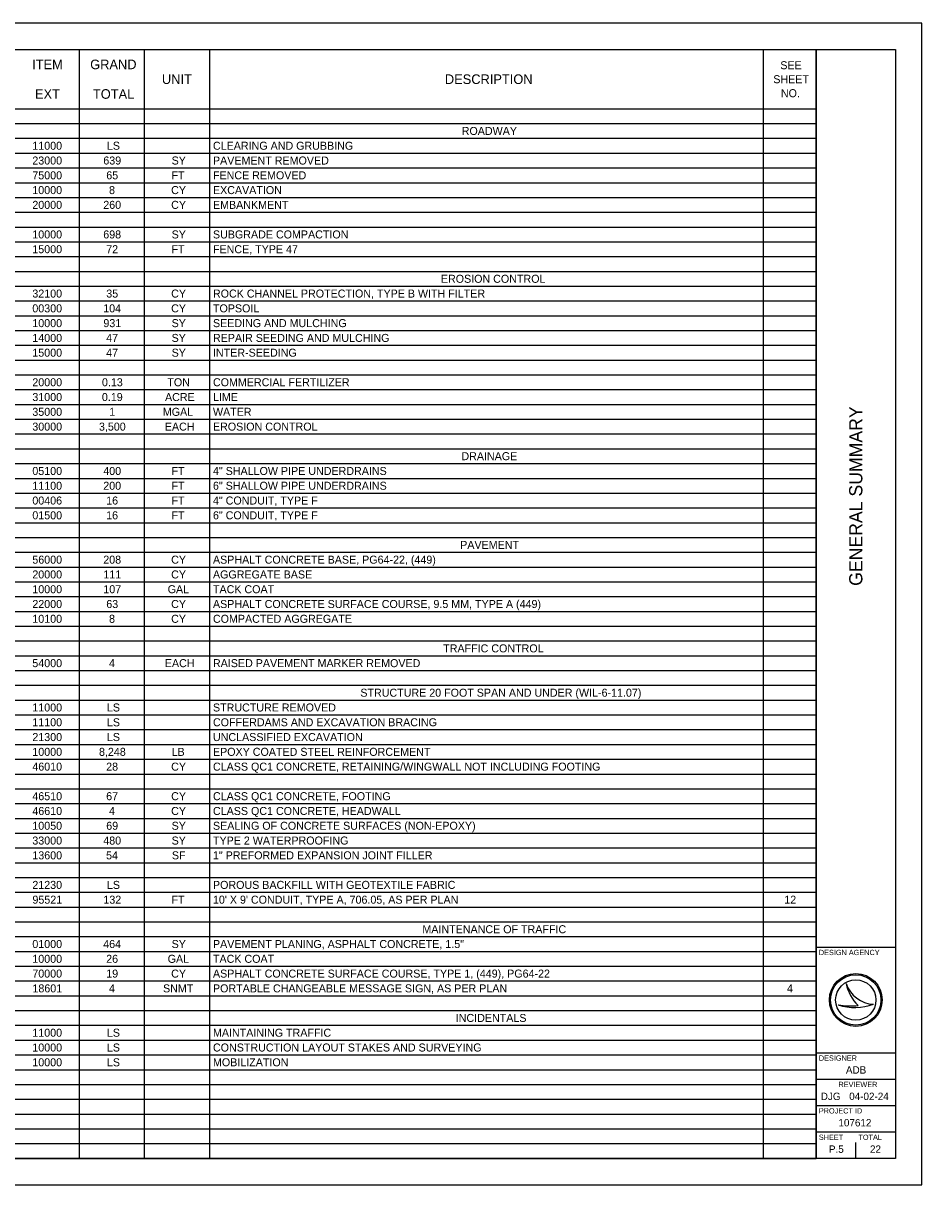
# Model space of a CAD drawing. Extents: x 0 to 34, y 0 to 22.
# Drawn here: x 16.98 to 34, y 0 to 22 of the extents above; entities that cross this region are included whole.
import ezdxf

# ---------------------------------------------------------------- set-up
doc = ezdxf.new("R2010")
doc.units = 0
for name, color, linetype in [('Default', 7, 'Continuous'), ('SH_Border', 7, 'Continuous'), ('SH_Cut_Line', 7, 'Continuous'), ('SH_Data', 7, 'Continuous')]:
    doc.layers.add(name, color=color, linetype=linetype)

msp = doc.modelspace()

# ---------------------------------------------------------------- linework, layer by layer
at = {"layer": 'Default'}
for p, q in [((1.5, 21.5), (32, 21.5)), ((18.035, 21.5), (18.035, 0.5)), ((19.27, 21.5), (19.27, 0.5)), ((20.505, 21.5), (20.505, 0.5)), ((30.995, 21.5), (30.995, 0.5)), ((32, 21.5), (32, 0.5)), ((1.5, 20.38), (32, 20.38)), ((1.5, 20.1), (32, 20.1)), ((1.5, 19.82), (32, 19.82)), ((1.5, 19.54), (32, 19.54)), ((1.5, 19.26), (32, 19.26)), ((1.5, 18.98), (32, 18.98)), ((1.5, 18.7), (32, 18.7)), ((1.5, 18.42), (32, 18.42)), ((1.5, 18.14), (32, 18.14)), ((1.5, 17.86), (32, 17.86)), ((1.5, 17.58), (32, 17.58)), ((1.5, 17.3), (32, 17.3)), ((1.5, 17.02), (32, 17.02)), ((1.5, 16.74), (32, 16.74)), ((1.5, 16.46), (32, 16.46)), ((1.5, 16.18), (32, 16.18)), ((1.5, 15.9), (32, 15.9)), ((1.5, 15.62), (32, 15.62)), ((1.5, 15.34), (32, 15.34)), ((1.5, 15.06), (32, 15.06)), ((1.5, 14.78), (32, 14.78)), ((1.5, 14.5), (32, 14.5)), ((1.5, 14.22), (32, 14.22)), ((1.5, 13.94), (32, 13.94)), ((1.5, 13.66), (32, 13.66)), ((1.5, 13.38), (32, 13.38)), ((1.5, 13.1), (32, 13.1)), ((1.5, 12.82), (32, 12.82)), ((1.5, 12.54), (32, 12.54)), ((1.5, 12.26), (32, 12.26)), ((1.5, 11.98), (32, 11.98)), ((1.5, 11.7), (32, 11.7)), ((1.5, 11.42), (32, 11.42)), ((1.5, 11.14), (32, 11.14)), ((1.5, 10.86), (32, 10.86)), ((1.5, 10.58), (32, 10.58)), ((1.5, 10.3), (32, 10.3)), ((1.5, 10.02), (32, 10.02)), ((1.5, 9.74), (32, 9.74)), ((1.5, 9.46), (32, 9.46)), ((1.5, 9.18), (32, 9.18)), ((1.5, 8.9), (32, 8.9)), ((1.5, 8.62), (32, 8.62)), ((1.5, 8.34), (32, 8.34)), ((1.5, 8.06), (32, 8.06)), ((1.5, 7.78), (32, 7.78)), ((1.5, 7.5), (32, 7.5)), ((1.5, 7.22), (32, 7.22)), ((1.5, 6.94), (32, 6.94)), ((1.5, 6.66), (32, 6.66)), ((1.5, 6.38), (32, 6.38)), ((1.5, 6.1), (32, 6.1)), ((1.5, 5.82), (32, 5.82)), ((1.5, 5.54), (32, 5.54)), ((1.5, 5.26), (32, 5.26)), ((1.5, 4.98), (32, 4.98)), ((1.5, 4.7), (32, 4.7)), ((1.5, 4.42), (32, 4.42)), ((1.5, 4.14), (32, 4.14)), ((1.5, 3.86), (32, 3.86)), ((1.5, 3.58), (32, 3.58)), ((1.5, 3.3), (32, 3.3)), ((1.5, 3.02), (32, 3.02)), ((1.5, 2.74), (32, 2.74)), ((1.5, 2.46), (32, 2.46)), ((1.5, 2.18), (32, 2.18)), ((1.5, 1.9), (32, 1.9)), ((1.5, 1.62), (32, 1.62)), ((1.5, 1.34), (32, 1.34)), ((1.5, 1.06), (32, 1.06)), ((1.5, 0.78), (32, 0.78)), ((1.5, 0.5), (32, 0.5))]:
    msp.add_line(p, q, dxfattribs=at)
at = {"layer": 'SH_Border'}
for p, q in [((32, 0.5), (32, 21.5)), ((32, 4.5), (33.5, 4.5)), ((32, 2.5), (33.5, 2.5)), ((32, 2), (33.5, 2)), ((32, 1.5), (33.5, 1.5)), ((32, 1), (33.5, 1))]:
    msp.add_line(p, q, dxfattribs=at)
msp.add_lwpolyline([(1.5, 21.5), (33.5, 21.5), (33.5, 0.5), (1.5, 0.5)], close=True, dxfattribs=at)
at = {"layer": 'SH_Cut_Line'}
msp.add_lwpolyline([(0, 0), (34, 0), (34, 22), (0, 22)], close=True, dxfattribs=at)
at = {"layer": 'SH_Data'}
for p, q in [((32.567, 3.81), (32.567, 3.81)), ((32.417, 3.41), (32.417, 3.41)), ((32.75, 3.5), (32.75, 3.5)), ((33.087, 3.419), (33.087, 3.419)), ((32.375, 0.675), (32.375, 0.675)), ((32.75, 0.5), (32.75, 0.8))]:
    msp.add_line(p, q, dxfattribs=at)
for radius in [0.5, 0.477, 0.477, 0.382]:
    msp.add_circle((32.75, 3.5), radius, dxfattribs=at)
for centre, radius, start, end in [((33.116, 3.998), 0.58, 198.9257, 198.9319), ((33.347, 3.97), 0.796, 191.6379, 191.6421), ((33.116, 3.998), 0.58, 198.9319, 267.1657), ((33.347, 3.97), 0.796, 191.6421, 226.0947), ((32.739, 4.37), 1.013, 251.4576, 290.0832), ((32.648, 4.654), 1.266, 259.4964, 259.4995), ((32.739, 4.37), 1.013, 251.4527, 251.4576), ((32.648, 4.654), 1.266, 259.4995, 276.6672)]:
    msp.add_arc(centre, radius, start, end, dxfattribs=at)

# ---------------------------------------------------------------- texts
at = {"layer": 'Default'}
for s, height, p in [('ITEM', 0.1818, (17.145, 21.129)), ('GRAND', 0.1818, (18.245, 21.129)), ('SEE ', 0.1515, (31.32, 21.129)), ('UNIT', 0.1818, (19.604, 20.849)), ('DESCRIPTION', 0.18184, (24.965, 20.849)), ('SHEET ', 0.1515, (31.187, 20.864)), ('EXT', 0.1818, (17.199, 20.569)), ('TOTAL', 0.1818, (18.297, 20.569)), ('NO.', 0.1515, (31.331, 20.599)), ('ROADWAY', 0.1515, (25.284, 19.884)), ('11000', 0.1515, (17.149, 19.604)), ('LS', 0.1515, (18.562, 19.604)), ('CLEARING AND GRUBBING', 0.15153, (20.571, 19.604)), ('23000', 0.1515, (17.149, 19.324)), ('639', 0.1515, (18.494, 19.324)), ('SY', 0.1515, (19.788, 19.324)), ('PAVEMENT REMOVED', 0.15153, (20.571, 19.324)), ('75000', 0.1515, (17.149, 19.044)), ('65', 0.1515, (18.55, 19.044)), ('FT', 0.1515, (19.786, 19.044)), ('FENCE REMOVED', 0.15153, (20.571, 19.044)), ('10000', 0.1515, (17.149, 18.764)), ('8', 0.152, (18.602, 18.764)), ('CY', 0.1515, (19.779, 18.764)), ('EXCAVATION', 0.1515, (20.571, 18.764)), ('20000', 0.1515, (17.149, 18.484)), ('260', 0.1515, (18.493, 18.484)), ('CY', 0.1515, (19.779, 18.484)), ('EMBANKMENT', 0.1515, (20.571, 18.484)), ('10000', 0.1515, (17.149, 17.924)), ('698', 0.1515, (18.493, 17.924)), ('SY', 0.1515, (19.788, 17.924)), ('SUBGRADE COMPACTION', 0.15153, (20.571, 17.924)), ('15000', 0.1515, (17.149, 17.644)), ('72', 0.1515, (18.549, 17.644)), ('FT', 0.1515, (19.786, 17.644)), ('FENCE, TYPE 47', 0.15153, (20.571, 17.644)), ('EROSION CONTROL', 0.15153, (24.889, 17.084)), ('32100', 0.1515, (17.149, 16.804)), ('35', 0.1515, (18.55, 16.804)), ('CY', 0.1515, (19.779, 16.804)), ('ROCK CHANNEL PROTECTION, TYPE B WITH FILTER', 0.15153, (20.571, 16.804)), ('00300', 0.1515, (17.149, 16.524)), ('104', 0.1515, (18.492, 16.524)), ('CY', 0.1515, (19.779, 16.524)), ('TOPSOIL', 0.1515, (20.571, 16.524)), ('10000', 0.1515, (17.149, 16.244)), ('931', 0.1515, (18.495, 16.244)), ('SY', 0.1515, (19.788, 16.244)), ('SEEDING AND MULCHING', 0.15153, (20.571, 16.244)), ('14000', 0.1515, (17.149, 15.964)), ('47', 0.1515, (18.548, 15.964)), ('SY', 0.1515, (19.788, 15.964)), ('REPAIR SEEDING AND MULCHING', 0.15153, (20.571, 15.964)), ('15000', 0.1515, (17.149, 15.684)), ('47', 0.1515, (18.548, 15.684)), ('SY', 0.1515, (19.788, 15.684)), ('INTER-SEEDING', 0.15153, (20.571, 15.684)), ('20000', 0.1515, (17.149, 15.124)), ('0.13', 0.1515, (18.468, 15.124)), ('TON', 0.1515, (19.707, 15.124)), ('COMMERCIAL FERTILIZER', 0.15153, (20.571, 15.124)), ('31000', 0.1515, (17.149, 14.844)), ('0.19', 0.1515, (18.467, 14.844)), ('ACRE', 0.1515, (19.663, 14.844)), ('LIME', 0.1515, (20.571, 14.844)), ('35000', 0.1515, (17.149, 14.564)), ('1', 0.152, (18.604, 14.564)), ('MGAL', 0.1515, (19.621, 14.564)), ('WATER', 0.1515, (20.571, 14.564)), ('30000', 0.1515, (17.149, 14.284)), ('3,500', 0.1515, (18.411, 14.284)), ('EACH', 0.1515, (19.659, 14.284)), ('EROSION CONTROL', 0.15153, (20.571, 14.284)), ('DRAINAGE', 0.1515, (25.278, 13.724)), ('05100', 0.1515, (17.149, 13.444)), ('400', 0.1515, (18.493, 13.444)), ('FT', 0.1515, (19.786, 13.444)), ('4" SHALLOW PIPE UNDERDRAINS', 0.15153, (20.571, 13.444)), ('11100', 0.1515, (17.149, 13.164)), ('200', 0.1515, (18.493, 13.164)), ('FT', 0.1515, (19.786, 13.164)), ('6" SHALLOW PIPE UNDERDRAINS', 0.15153, (20.571, 13.164)), ('00406', 0.1515, (17.149, 12.884)), ('16', 0.1515, (18.548, 12.884)), ('FT', 0.1515, (19.786, 12.884)), ('4" CONDUIT, TYPE F', 0.15153, (20.571, 12.884)), ('01500', 0.1515, (17.149, 12.604)), ('16', 0.1515, (18.548, 12.604)), ('FT', 0.1515, (19.786, 12.604)), ('6" CONDUIT, TYPE F', 0.15153, (20.571, 12.604)), ('PAVEMENT', 0.1515, (25.255, 12.044)), ('56000', 0.1515, (17.149, 11.764)), ('208', 0.1515, (18.493, 11.764)), ('CY', 0.1515, (19.779, 11.764)), ('ASPHALT CONCRETE BASE, PG64-22, (449)', 0.15153, (20.571, 11.764)), ('20000', 0.1515, (17.149, 11.484)), ('111', 0.1515, (18.495, 11.484)), ('CY', 0.1515, (19.779, 11.484)), ('AGGREGATE BASE', 0.15153, (20.571, 11.484)), ('10000', 0.1515, (17.149, 11.204)), ('107', 0.1515, (18.494, 11.204)), ('GAL', 0.1515, (19.713, 11.204)), ('TACK COAT', 0.1515, (20.571, 11.204)), ('22000', 0.1515, (17.149, 10.924)), ('63', 0.1515, (18.55, 10.924)), ('CY', 0.1515, (19.779, 10.924)), ('ASPHALT CONCRETE SURFACE COURSE, 9.5 MM, TYPE A (449)', 0.15153, (20.571, 10.924)), ('10100', 0.1515, (17.149, 10.644)), ('8', 0.152, (18.602, 10.644)), ('CY', 0.1515, (19.779, 10.644)), ('COMPACTED AGGREGATE', 0.15153, (20.571, 10.644)), ('TRAFFIC CONTROL', 0.15153, (24.933, 10.084)), ('54000', 0.1515, (17.149, 9.804)), ('4', 0.152, (18.601, 9.804)), ('EACH', 0.1515, (19.659, 9.804)), ('RAISED PAVEMENT MARKER REMOVED', 0.15153, (20.571, 9.804)), ('STRUCTURE 20 FOOT SPAN AND UNDER (WIL-6-11.07)', 0.15153, (23.363, 9.244)), ('11000', 0.1515, (17.149, 8.964)), ('LS', 0.1515, (18.562, 8.964)), ('STRUCTURE REMOVED', 0.15153, (20.571, 8.964)), ('11100', 0.1515, (17.149, 8.684)), ('LS', 0.1515, (18.562, 8.684)), ('COFFERDAMS AND EXCAVATION BRACING', 0.15153, (20.571, 8.684)), ('21300', 0.1515, (17.149, 8.404)), ('LS', 0.1515, (18.562, 8.404)), ('UNCLASSIFIED EXCAVATION', 0.15153, (20.571, 8.404)), ('10000', 0.1515, (17.149, 8.124)), ('8,248', 0.1515, (18.412, 8.124)), ('LB', 0.1515, (19.788, 8.124)), ('EPOXY COATED STEEL REINFORCEMENT', 0.15153, (20.571, 8.124)), ('46010', 0.1515, (17.149, 7.844)), ('28', 0.1515, (18.548, 7.844)), ('CY', 0.1515, (19.779, 7.844)), ('CLASS QC1 CONCRETE, RETAINING/WINGWALL NOT INCLUDING FOOTING', 0.15153, (20.571, 7.844)), ('46510', 0.1515, (17.149, 7.284)), ('67', 0.1515, (18.548, 7.284)), ('CY', 0.1515, (19.779, 7.284)), ('CLASS QC1 CONCRETE, FOOTING', 0.15153, (20.571, 7.284)), ('46610', 0.1515, (17.149, 7.004)), ('4', 0.152, (18.601, 7.004)), ('CY', 0.1515, (19.779, 7.004)), ('CLASS QC1 CONCRETE, HEADWALL', 0.15153, (20.571, 7.004)), ('10050', 0.1515, (17.149, 6.724)), ('69', 0.1515, (18.549, 6.724)), ('SY', 0.1515, (19.788, 6.724)), ('SEALING OF CONCRETE SURFACES (NON-EPOXY)', 0.15153, (20.571, 6.724)), ('33000', 0.1515, (17.149, 6.444)), ('480', 0.1515, (18.493, 6.444)), ('SY', 0.1515, (19.788, 6.444)), ('TYPE 2 WATERPROOFING', 0.15153, (20.571, 6.444)), ('13600', 0.1515, (17.149, 6.164)), ('54', 0.1515, (18.546, 6.164)), ('SF', 0.1515, (19.793, 6.164)), ('1" PREFORMED EXPANSION JOINT FILLER', 0.15153, (20.571, 6.164)), ('21230', 0.1515, (17.149, 5.604)), ('LS', 0.1515, (18.562, 5.604)), ('POROUS BACKFILL WITH GEOTEXTILE FABRIC', 0.15153, (20.571, 5.604)), ('95521', 0.1515, (17.151, 5.324)), ('132', 0.1515, (18.495, 5.324)), ('FT', 0.1515, (19.786, 5.324)), ("10' X 9' CONDUIT, TYPE A, 706.05, AS PER PLAN", 0.15153, (20.571, 5.324)), ('12', 0.1515, (31.395, 5.324)), ('MAINTENANCE OF TRAFFIC', 0.15153, (24.539, 4.764)), ('01000', 0.1515, (17.149, 4.484)), ('464', 0.1515, (18.492, 4.484)), ('SY', 0.1515, (19.788, 4.484)), ('PAVEMENT PLANING, ASPHALT CONCRETE, 1.5"', 0.15153, (20.571, 4.484)), ('10000', 0.1515, (17.149, 4.204)), ('26', 0.1515, (18.548, 4.204)), ('GAL', 0.1515, (19.713, 4.204)), ('TACK COAT', 0.1515, (20.571, 4.204)), ('70000', 0.1515, (17.149, 3.924)), ('19', 0.1515, (18.549, 3.924)), ('CY', 0.1515, (19.779, 3.924)), ('ASPHALT CONCRETE SURFACE COURSE, TYPE 1, (449), PG64-22', 0.15153, (20.571, 3.924)), ('18601', 0.1515, (17.151, 3.644)), ('4', 0.152, (18.601, 3.644)), ('SNMT', 0.1515, (19.625, 3.644)), ('PORTABLE CHANGEABLE MESSAGE SIGN, AS PER PLAN', 0.15153, (20.571, 3.644)), ('4', 0.152, (31.446, 3.644)), ('INCIDENTALS', 0.15153, (25.171, 3.084)), ('11000', 0.1515, (17.149, 2.804)), ('LS', 0.1515, (18.562, 2.804)), ('MAINTAINING TRAFFIC', 0.15153, (20.571, 2.804)), ('10000', 0.1515, (17.149, 2.524)), ('LS', 0.1515, (18.562, 2.524)), ('CONSTRUCTION LAYOUT STAKES AND SURVEYING', 0.15153, (20.571, 2.524)), ('10000', 0.1515, (17.149, 2.244)), ('LS', 0.1515, (18.562, 2.244)), ('MOBILIZATION', 0.15153, (20.571, 2.244))]:
    msp.add_text(s, height=height, dxfattribs=at).set_placement(p)
at = {"layer": 'SH_Data'}
msp.add_text('GENERAL SUMMARY', height=0.25, rotation=90, dxfattribs=at).set_placement((32.875, 11.344))
for s, height, p in [('DESIGN AGENCY', 0.1, (32.05, 4.35)), ('DESIGNER', 0.1, (32.05, 2.35)), ('ADB', 0.14, (32.563, 2.105)), ('REVIEWER', 0.1, (32.422, 1.85)), ('DJG', 0.14, (32.087, 1.605)), ('04-02-24', 0.14, (32.625, 1.605)), ('PROJECT ID', 0.1, (32.05, 1.35)), ('107612', 0.14, (32.421, 1.105)), ('SHEET', 0.1, (32.05, 0.85)), ('TOTAL', 0.1, (32.8, 0.85)), ('P.5', 0.14, (32.241, 0.605)), ('22', 0.14, (33.019, 0.605))]:
    msp.add_text(s, height=height, dxfattribs=at).set_placement(p)

doc.saveas('drawing.dxf')
